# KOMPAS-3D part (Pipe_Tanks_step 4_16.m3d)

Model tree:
1. X Axis
2. Y Axis
3. Z Axis  (labels: Bend 90 Dn 150; Pipe Dn 150)
     Òîëùèíà ñòåíêè 1 = 1

Referenced files in C:\Documents and Settings\kashirsky\Мои документы\Camtasia Studio\Pipelines3D\Tanks\: Tanks_step 4.a3d
Referenced files in C:\Program Files\ASCON\KOMPAS-3D V10\Libs\Piping\LOAD\: Piping_C_Pipe_150_1000.m3d
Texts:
  Pipe Dn 150
  Steel ASTM A295
  Three Point Plane
  Plane at Angle
  Line and Point Plane
  Axis through Two Vertices
  Axis of Feature
  Axis of Conical Surface
  Axis through Edge
  Trim by Surface
  Trim by Sketch
  Feature with No History
  Intersection Axis of Two Planes
  Two Line Plane
  Line and Face Plane
  Bend by line
  Hole in sheet body
  Cut in sheet body
  Point in CM
  Linear Dimension from Line to Point
  Surface Finish Symbol
  Geometric Tolerance Symbol
  Leader #1
  Leader #2
  Leader #3
  Shape Deviations and Datum
  Node point number
  Mark of coordination axis
  Node point designation
  Mark/Reference designation with leader
  Mark/reference designation on line
  Mark/Reference designation without leader
  Bend 90 Dn 150
  Plane of section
